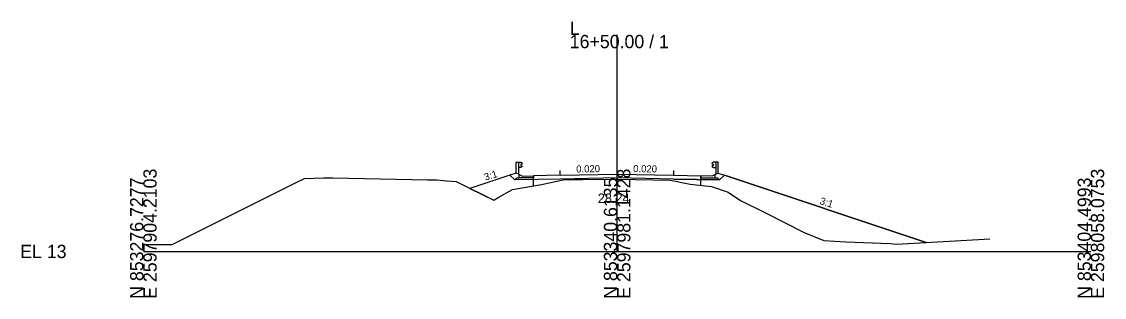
# Model space of a CAD drawing. Extents: x -26 to 1203, y -10 to 9526.
# Drawn here: x -25.7 to 202.8, y 6490.3 to 6548.5 of the extents above; entities that cross this region are included whole.
import ezdxf

# ---------------------------------------------------------------- set-up
doc = ezdxf.new("R2010")
doc.units = 0
for name, color, linetype in [('Exist Cross Section Cell', 7, 'Continuous'), ('Exist XS Center Line Elevation Label', 7, 'Continuous'), ('Exist XS Ground Line', 7, 'Continuous'), ('Prop XS Earthwork Shape', 7, 'Continuous'), ('Prop XS EOT Tick Mark', 7, 'Continuous'), ('Prop XS Finish Grade', 7, 'Continuous'), ('Prop XS Finish Grade Earthwork', 7, 'Continuous'), ('Prop XS Finish Grade Paved Shoulder', 7, 'Continuous'), ('Prop XS Finish Grade Pavement', 7, 'Continuous'), ('Prop XS Guardrail', 7, 'Continuous'), ('Prop XS Pvmt Edge Slope', 7, 'Continuous'), ('Prop XS SBG', 7, 'Continuous'), ('Prop XS SE Text', 7, 'Continuous'), ('Prop XS Side Slope Text', 7, 'Continuous'), ('Prop XS Subgrade Earthwork', 7, 'Continuous'), ('Scratch_Level_5', 7, 'Continuous')]:
    doc.layers.add(name, color=color, linetype=linetype)

msp = doc.modelspace()

# ---------------------------------------------------------------- linework, layer by layer
at = {"layer": 'Exist Cross Section Cell'}
for p, q in [((100, 6500), (100, 6545.73)), ((0, 6500), (100, 6500)), ((100, 6500), (200, 6500))]:
    msp.add_line(p, q, dxfattribs=at)
at = {"layer": 'Exist XS Ground Line'}
for p, q in [((34, 6515.42), (36, 6515.5)), ((36, 6515.5), (38, 6515.58)), ((38, 6515.58), (40, 6515.54)), ((40, 6515.54), (50, 6515.34)), ((6.05, 6501.45), (32.13, 6514.49)), ((32.13, 6514.49), (34, 6515.42)), ((50, 6515.34), (60, 6515.14)), ((60, 6515.14), (62, 6515.1)), ((62, 6515.1), (64, 6514.94)), ((64, 6514.94), (66, 6514.78)), ((66, 6514.78), (73.94, 6510.82)), ((77.91, 6513.11), (84.03, 6514.17)), ((84.03, 6514.17), (88.88, 6515.17)), ((88.88, 6515.17), (92.7, 6515.2)), ((92.7, 6515.2), (100.19, 6515.24)), ((100.19, 6515.24), (107.55, 6515.1)), ((107.55, 6515.1), (111.23, 6515.04)), ((111.23, 6515.04), (115.4, 6514.19)), ((115.4, 6514.19), (119.9, 6513.73)), ((119.9, 6513.73), (123.44, 6512.55)), ((73.94, 6510.82), (74.88, 6511.38)), ((74.88, 6511.38), (77.91, 6513.11)), ((123.44, 6512.55), (126.03, 6510.75)), ((126.03, 6510.75), (131.29, 6508.13)), ((131.29, 6508.13), (139.5, 6504)), ((139.5, 6504), (143.61, 6502.31)), ((143.61, 6502.31), (148.24, 6502.03)), ((148.24, 6502.03), (157.62, 6501.65)), ((158.94, 6501.57), (176.28, 6502.54)), ((176.28, 6502.54), (178.66, 6502.66)), ((0, 6501.46), (6.05, 6501.45)), ((157.62, 6501.65), (158.94, 6501.57))]:
    msp.add_line(p, q, dxfattribs=at)
at = {"layer": 'Prop XS Earthwork Shape'}
msp.add_lwpolyline([(78.38, 6515.11), (77.36, 6516.13), (68.93, 6513.32), (73.94, 6510.82), (74.88, 6511.38), (77.91, 6513.11), (84.03, 6514.17), (88.88, 6515.17), (92.7, 6515.2), (100.19, 6515.24), (107.55, 6515.1), (111.23, 6515.04), (115.4, 6514.19), (119.9, 6513.73), (123.44, 6512.55), (126.03, 6510.75), (131.29, 6508.13), (139.5, 6504), (143.61, 6502.31), (148.24, 6502.03), (157.62, 6501.65), (158.94, 6501.57), (165.26, 6501.92), (122.64, 6516.13), (121.62, 6515.11), (112, 6515.3), (100, 6515.54), (88, 6515.3)], close=True, dxfattribs=at)
at = {"layer": 'Prop XS EOT Tick Mark'}
for p, q in [((88, 6516.1), (88, 6517.1)), ((112, 6516.1), (112, 6517.1))]:
    msp.add_line(p, q, dxfattribs=at)
at = {"layer": 'Prop XS Finish Grade'}
for p, q in [((78.67, 6516.56), (77.36, 6516.13)), ((79.33, 6516.23), (78.69, 6516.55)), ((120.67, 6516.23), (121.31, 6516.55)), ((121.33, 6516.56), (122.64, 6516.13))]:
    msp.add_line(p, q, dxfattribs=at)
at = {"layer": 'Prop XS Finish Grade Earthwork'}
for p, q in [((77.36, 6516.13), (68.93, 6513.32)), ((122.64, 6516.13), (165.26, 6501.92))]:
    msp.add_line(p, q, dxfattribs=at)
at = {"layer": 'Prop XS Finish Grade Paved Shoulder'}
for p, q in [((88, 6516.1), (82.33, 6515.98)), ((112, 6516.1), (117.67, 6515.98))]:
    msp.add_line(p, q, dxfattribs=at)
at = {"layer": 'Prop XS Finish Grade Pavement'}
for p, q in [((88, 6516.1), (100, 6516.34)), ((100, 6516.34), (112, 6516.1))]:
    msp.add_line(p, q, dxfattribs=at)
at = {"layer": 'Prop XS Guardrail'}
for p, q in [((78.67, 6516.56), (78.67, 6518.86)), ((78.67, 6518.86), (79.17, 6518.86)), ((79.17, 6518.86), (79.17, 6516.31)), ((79.17, 6518.86), (79.67, 6518.86)), ((79.67, 6518.86), (79.96, 6518.66)), ((79.96, 6518.54), (79.67, 6518.34)), ((79.67, 6518.34), (79.67, 6518.24)), ((79.67, 6518.24), (79.96, 6518.04)), ((79.96, 6517.92), (79.67, 6517.72)), ((79.96, 6518.66), (79.99, 6518.6)), ((79.99, 6518.6), (79.96, 6518.54)), ((79.96, 6518.04), (79.99, 6517.98)), ((79.99, 6517.98), (79.96, 6517.92)), ((120.04, 6518.66), (120.01, 6518.6)), ((120.01, 6518.6), (120.04, 6518.54)), ((120.04, 6518.04), (120.01, 6517.98)), ((120.01, 6517.98), (120.04, 6517.92)), ((120.33, 6518.86), (120.04, 6518.66)), ((120.04, 6518.54), (120.33, 6518.34)), ((120.33, 6518.24), (120.04, 6518.04)), ((120.04, 6517.92), (120.33, 6517.72)), ((120.83, 6518.86), (120.33, 6518.86)), ((120.33, 6518.34), (120.33, 6518.24)), ((121.33, 6518.86), (120.83, 6518.86)), ((120.83, 6518.86), (120.83, 6516.31)), ((121.33, 6516.56), (121.33, 6518.86)), ((79.67, 6517.72), (79.17, 6517.72)), ((120.33, 6517.72), (120.83, 6517.72))]:
    msp.add_line(p, q, dxfattribs=at)
at = {"layer": 'Prop XS Pvmt Edge Slope'}
for p, q in [((78.83, 6515.57), (78.38, 6515.11)), ((78.83, 6515.57), (79.33, 6515.57)), ((120.67, 6515.57), (121.17, 6515.57)), ((121.17, 6515.57), (121.62, 6515.11))]:
    msp.add_line(p, q, dxfattribs=at)
at = {"layer": 'Prop XS SBG'}
for p, q in [((79.33, 6515.57), (79.33, 6516.23)), ((79.33, 6516.23), (80, 6515.9)), ((82.33, 6515.57), (79.33, 6515.57)), ((80, 6515.9), (82.33, 6515.98)), ((82.33, 6515.98), (82.33, 6515.57)), ((117.67, 6515.98), (117.67, 6515.57)), ((120, 6515.9), (117.67, 6515.98)), ((117.67, 6515.57), (120.67, 6515.57)), ((120.67, 6516.23), (120, 6515.9)), ((120.67, 6515.57), (120.67, 6516.23))]:
    msp.add_line(p, q, dxfattribs=at)
at = {"layer": 'Prop XS Subgrade Earthwork'}
for p, q in [((78.38, 6515.11), (77.36, 6516.13)), ((100, 6515.54), (88, 6515.3)), ((112, 6515.3), (100, 6515.54)), ((121.62, 6515.11), (122.64, 6516.13)), ((88, 6515.3), (78.38, 6515.11)), ((112, 6515.3), (121.62, 6515.11))]:
    msp.add_line(p, q, dxfattribs=at)
at = {"layer": 'Scratch_Level_5'}
for p, q in [((82.33, 6513.88), (82.33, 6515.98)), ((100, 6515.25), (100, 6516.34)), ((117.67, 6513.96), (117.67, 6515.98))]:
    msp.add_line(p, q, dxfattribs=at)

# ---------------------------------------------------------------- texts
at = {"layer": 'Exist Cross Section Cell'}
for s, p in [('L', (90, 6545.73)), ('16+50.00 / 1', (90, 6542.93)), ('EL 13', (-26, 6498.6))]:
    msp.add_text(s, height=2.8, dxfattribs=at).set_placement(p)
for s, p in [('E 2597904.2103', (2.8, 6490)), ('E 2597981.1428', (102.8, 6490)), ('E 2598058.0753', (202.8, 6490)), ('N 853276.7277', (0, 6490)), ('N 853340.6135', (100, 6490)), ('N 853404.4993', (200, 6490))]:
    msp.add_text(s, height=2.8, rotation=90, dxfattribs=at).set_placement(p)
at = {"layer": 'Exist XS Center Line Elevation Label'}
msp.add_text('28.24', height=2, dxfattribs=at).set_placement((95.93, 6510.24))
at = {"layer": 'Prop XS SE Text'}
for rotation, p in [(1.1458, (91.38, 6516.66)), (358.8542, (103.38, 6516.77))]:
    msp.add_text('0.020', height=1.5, rotation=rotation, dxfattribs=at).set_placement(p)
at = {"layer": 'Prop XS Side Slope Text'}
for rotation, p in [(16.5928, (72.18, 6514.95)), (341.9127, (142.66, 6510.06))]:
    msp.add_text('3:1', height=1.5, rotation=rotation, dxfattribs=at).set_placement(p)

doc.saveas('drawing.dxf')
